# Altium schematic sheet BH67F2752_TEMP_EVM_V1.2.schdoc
size 304 x 228 mm; PageSetup: Record=PageOptions¦CenterHorizontal=True¦CenterVertical=True¦PrintScale=0.87¦XCorrection=1.00¦YCorrection=1.00¦PrintKind=1¦BorderSize=5000000¦LeftOffset=0¦BottomOffset=0¦Orientation=2¦PaperLength=2970¦PaperWidth=2100¦Scale=100¦PaperSource=7¦PrintQuality=600¦MediaType=1¦DitherType=10¦PaperKind=A4¦PrintScaleMode=1
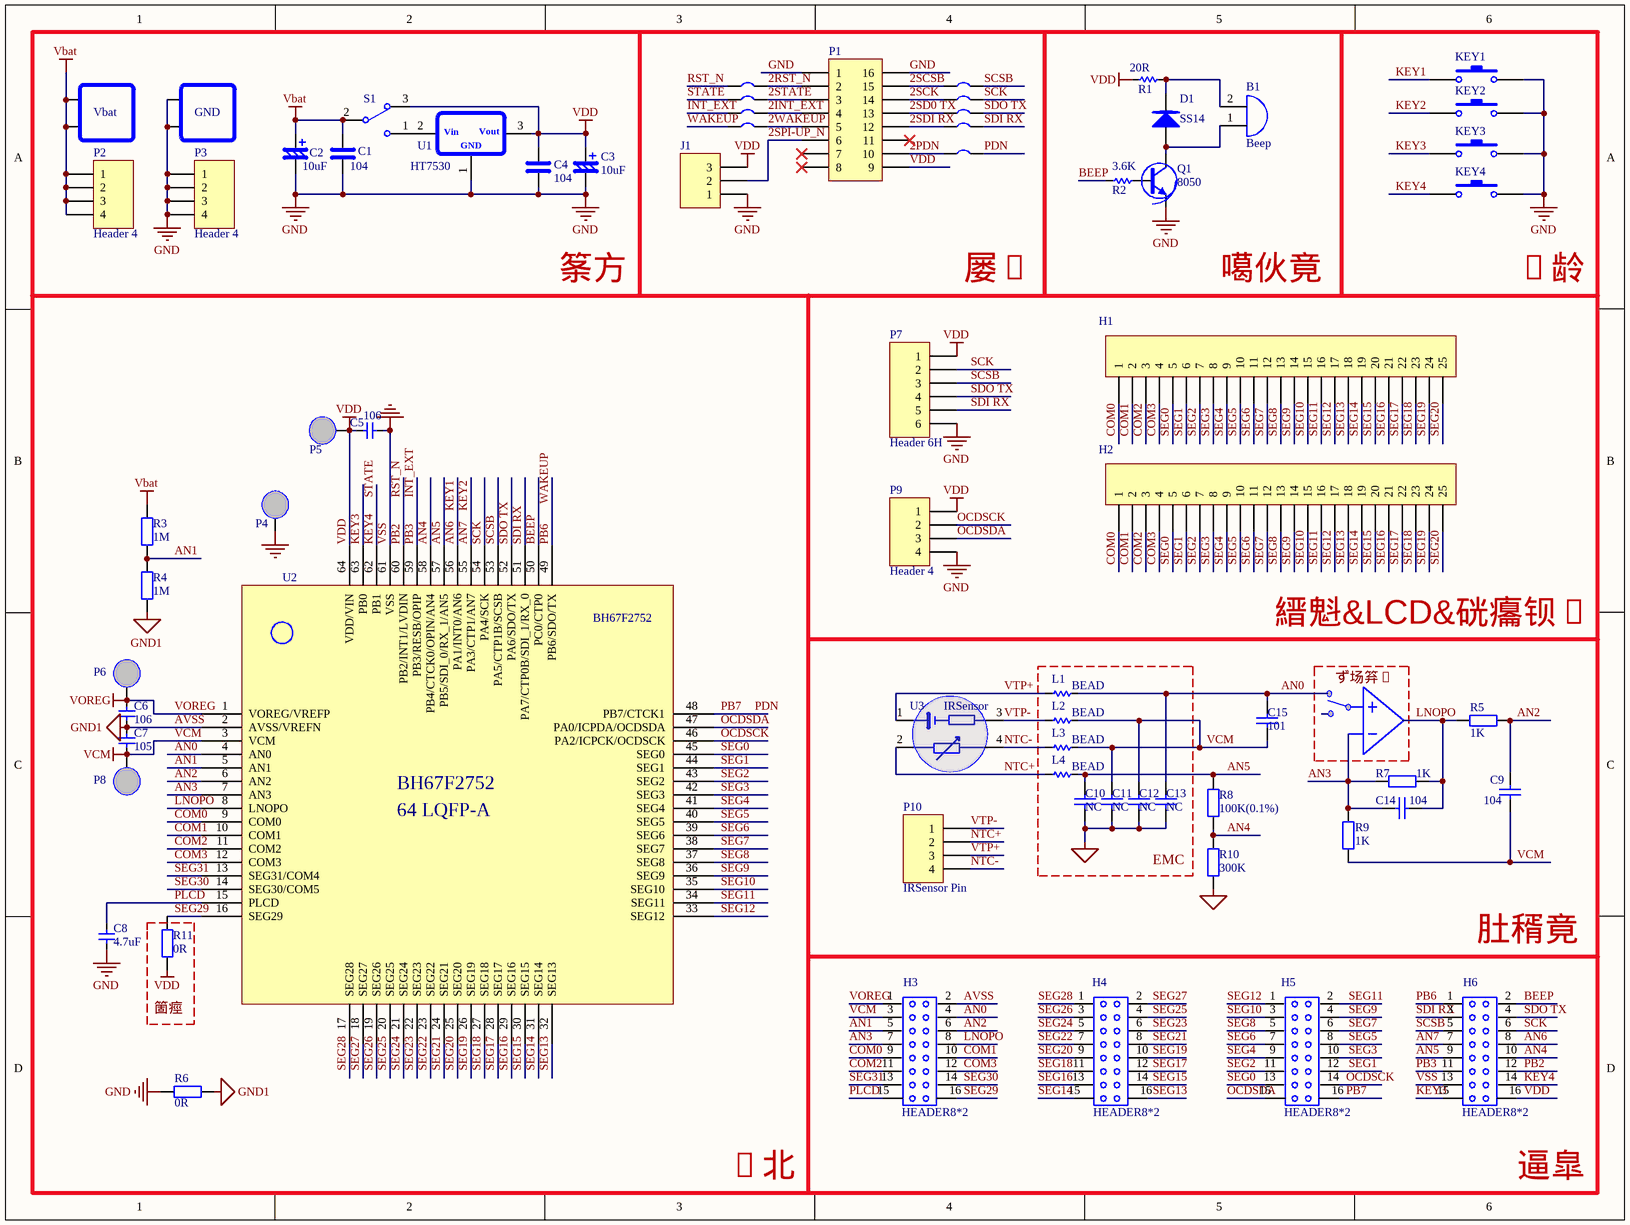
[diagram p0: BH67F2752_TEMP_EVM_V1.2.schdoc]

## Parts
B1  Beep  [BEEP_12mm]
C1  value 104  [C0805]  (hidden comment: CAPACITOR)
C2  Vaule: 10uF  [C0805]  (hidden comment: ECAP)
C3  Vaule: 10uF  [C0805]  (hidden comment: ECAP)
C4  value 104  [C0805]  (hidden comment: CAPACITOR)
C5  106  [CAP_0603]
C6  106  [CAP_0603]
C7  105  [CAP_0603]
C8  4.7uF  [CAP_0603]
C9  104  [CAP_0603]
C10  NC  [CAP_0603]
C11  NC  [CAP_0603]
C12  NC  [CAP_0603]
C13  NC  [CAP_0603]
C14  104  [CAP_0603]
C15  101  [CAP_0603]
D1  SS14  [DIODE]
GND  CONNET*2  [CLIP POWER PIN]  (value not drawn)  (no BOM)
H1  HEADER36  [Header25(2mm) - duplicate]  (value not drawn)
H2  HEADER36  [Header252.54mm)]  (value not drawn)
H3  HEADER8*2  [HEAD2X8]  (no BOM)
H4  HEADER8*2  [2HEAD2X8]  (no BOM)
H5  HEADER8*2  [3HEAD2X8]  (no BOM)
H6  HEADER8*2  [4HEAD2X8 - duplicate]  (no BOM)
INT_EX1  JUMPER  [JUMP_2]  (value not drawn)  (no BOM)
J1  Header 3  [JUMP_3]  (value not drawn)
KEY1  SW-PB  [AN66]  (value not drawn)
KEY2  SW-PB  [AN66]  (value not drawn)
KEY3  SW-PB  [AN66]  (value not drawn)
KEY4  SW-PB  [AN66]  (value not drawn)
L1  BEAD  [RES_0603]
L2  BEAD  [RES_0603]
L3  BEAD  [RES_0603]
L4  BEAD  [RES_0603]
P1  Header 8X2A  [BC7602]  (value not drawn)
P2  Header 4  [HDR1X4]
P3  Header 4  [HDR1X4]
P4  PAD  [PAD]  (value not drawn)
P5  PAD  [PAD]  (value not drawn)
P6  PAD  [PAD]  (value not drawn)
P7  Header 6H  [HEAD1X6]
P8  PAD  [PAD]  (value not drawn)
P9  Header 4  [HDR1X4]
P10  IRSensor Pin  [HDR1X4]
PDN1  JUMPER  [JUMP_2]  (value not drawn)  (no BOM)
Q1  8050  [SOT-23]
R1  20R  [RES_0603]
R2  3.6K  [RES_0603]
R3  value 1M  [RES_0603]  (hidden comment: RES0603)
R4  value 1M  [RES_0603]  (hidden comment: RES0603)
R5  value 1K  [RES_0603]  (hidden comment: RES0603)
R6  value 0R  [RES_0603]  (hidden comment: RES0603)
R7  value 1K  [RES_0603]  (hidden comment: RES0603)
R8  value 100K(0.1%)  [RES_0603]  (hidden comment: RES0603)
R9  value 1K  [RES_0603]  (hidden comment: RES0603)
R10  value 300K  [RES_0603]  (hidden comment: RES0603)
R11  value 0R  [RES_0603]  (hidden comment: RES0603)
RST_N1  JUMPER  [JUMP_2]  (value not drawn)  (no BOM)
S1  SW-3  [JUMP_3]  (value not drawn)
SCK1  JUMPER  [JUMP_2]  (value not drawn)  (no BOM)
SCS1  JUMPER  [JUMP_2]  (value not drawn)  (no BOM)
SDIRX1  JUMPER  [JUMP_2]  (value not drawn)  (no BOM)
SDOTX1  JUMPER  [JUMP_2]  (value not drawn)  (no BOM)
STATE1  JUMPER  [JUMP_2]  (value not drawn)  (no BOM)
U1  HT7530  [SOT89M]
U2  BH67F2752  [64PIN(LQFP)]
U3  IRSensor  [TS318_115]
Vbat  CONNET*2  [CLIP POWER PIN]  (value not drawn)  (no BOM)
WAKE1  JUMPER  [JUMP_2]  (value not drawn)  (no BOM)

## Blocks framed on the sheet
EMC: C10-C13 L1-L4
箇痙: R11

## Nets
AVSS: C6.2 C7.1 C10.2 C11.2 C12.2 C13.2 H3.2 R4.2 R6.1 R10.2 U2.2(AVSS/VREFN)  [also labelled GND1]
GND: C1.1 C2.2 C3.2 C4.1 C5.1 C8.2 GND.1 GND.2 H6.13 J1.1 KEY1.2 KEY2.2 KEY3.2 KEY4.2 P1.1 P1.16 P3.1 P3.2 P3.3 P3.4 P4.1 P7.6 P9.4 Q1.2(E) R6.2 U1.1 U2.61(VSS)  [also labelled VSS]
Vbat: C1.2 C2.1 P2.1 P2.2 P2.3 P2.4 R3.1 S1.2 Vbat.1 Vbat.2
VCM: C7.2 C9.1 C11.1 C12.1 C15.2 H3.3 L2.2 L3.2 P8.1 R9.1 U2.3(VCM)
VDD: C3.1 C4.2 C5.2 H6.16 J1.3 P1.9 P5.1 P7.1 P9.1 R1.2 S1.3 U1.3 U2.64(VDD/VIN)
VOREG: C6.1 H3.1 P6.1 U2.1(VOREG/VREFP)
2INT_EXT: INT_EX1.2 P1.4
2PDN: P1.10 PDN1.2
2RST_N: P1.2 RST_N1.2
2SCK: P1.14 SCK1.2
2SCSB: P1.15 SCS1.2
2SD0 TX: P1.13 SDOTX1.2
2SDI RX: P1.12 SDIRX1.2
2SPI-UP_N: J1.2 P1.6
2STATE: P1.3 STATE1.2
2WAKEUP: P1.5 WAKE1.2
AN0: C13.1 C15.1 H3.4 L1.2 U2.4(AN0)
AN1: H3.5 R3.2 R4.1 U2.5(AN1)
AN2: C9.2 H3.6 R5.2 U2.6(AN2)
AN3: C14.2 H3.7 R7.1 R9.2 U2.7(AN3)
AN4: H6.10 R8.2 R10.1 U2.58(PB4/CTCK0/OPIN/AN4)
AN5: C10.1 H6.9 L4.2 R8.1 U2.57(PB5/SDI_0/RX_1/AN5)
AN6: H6.8 KEY1.1 U2.56(PA1/INT0/AN6)  [also labelled KEY1]
AN7: H6.7 KEY2.1 U2.55(PA3/CTP1/AN7)  [also labelled KEY2]
BEEP: H6.2 R2.1 U2.50(PC0/CTP0)
COM0: H1.1 H2.1 H3.9 U2.9(COM0)
COM1: H1.2 H2.2 H3.10 U2.10(COM1)
COM2: H1.3 H2.3 H3.11 U2.11(COM2)
COM3: H1.4 H2.4 H3.12 U2.12(COM3)
INT_EXT: H6.11 INT_EX1.1 U2.59(PB3/RESB/OPIP)  [also labelled PB3]
KEY3: H6.15 KEY3.1 U2.63(PB0)
KEY4: H6.14 KEY4.1 STATE1.1 U2.62(PB1)  [also labelled STATE]
LNOPO: C14.1 H3.8 R5.1 R7.2 U2.8(LNOPO)
NTC+: L4.1 P10.2 U3.2
NTC-: L3.1 P10.4 U3.4
OCDSCK: H5.14 P9.2 U2.46(PA2/ICPCK/OCDSCK)
OCDSDA: H5.15 P9.3 U2.47(PA0/ICPDA/OCDSDA)
PB2: H6.12 RST_N1.1 U2.60(PB2/INT1/LVDIN)  [also labelled RST_N]
PB6: H6.1 U2.49(PB6/SDO/TX) WAKE1.1  [also labelled WAKEUP]
PB7: H5.16 PDN1.1 U2.48(PB7/CTCK1)  [also labelled PDN]
PLCD: C8.1 H3.15 U2.15(PLCD)
SCK: H6.6 P7.2 SCK1.1 U2.54(PA4/SCK)
SCSB: H6.5 P7.3 SCS1.1 U2.53(PA5/CTP1B/SCSB)
SDI RX: H6.3 P7.5 SDIRX1.1 U2.51(PA7/CTP0B/SDI_1/RX_0)
SDO TX: H6.4 P7.4 SDOTX1.1 U2.52(PA6/SDO/TX)
SEG0: H1.5 H2.5 H5.13 U2.45(SEG0)
SEG1: H1.6 H2.6 H5.12 U2.44(SEG1)
SEG2: H1.7 H2.7 H5.11 U2.43(SEG2)
SEG3: H1.8 H2.8 H5.10 U2.42(SEG3)
SEG4: H1.9 H2.9 H5.9 U2.41(SEG4)
SEG5: H1.10 H2.10 H5.8 U2.40(SEG5)
SEG6: H1.11 H2.11 H5.7 U2.39(SEG6)
SEG7: H1.12 H2.12 H5.6 U2.38(SEG7)
SEG8: H1.13 H2.13 H5.5 U2.37(SEG8)
SEG9: H1.14 H2.14 H5.4 U2.36(SEG9)
SEG10: H1.15 H2.15 H5.3 U2.35(SEG10)
SEG11: H1.16 H2.16 H5.2 U2.34(SEG11)
SEG12: H1.17 H2.17 H5.1 U2.33(SEG12)
SEG13: H1.18 H2.18 H4.16 U2.32(SEG13)
SEG14: H1.19 H2.19 H4.15 U2.31(SEG14)
SEG15: H1.20 H2.20 H4.14 U2.30(SEG15)
SEG16: H1.21 H2.21 H4.13 U2.29(SEG16)
SEG17: H1.22 H2.22 H4.12 U2.28(SEG17)
SEG18: H1.23 H2.23 H4.11 U2.27(SEG18)
SEG19: H1.24 H2.24 H4.10 U2.26(SEG19)
SEG20: H1.25 H2.25 H4.9 U2.25(SEG20)
SEG21: H4.8 U2.24(SEG21)
SEG22: H4.7 U2.23(SEG22)
SEG23: H4.6 U2.22(SEG23)
SEG24: H4.5 U2.21(SEG24)
SEG25: H4.4 U2.20(SEG25)
SEG26: H4.3 U2.19(SEG26)
SEG27: H4.2 U2.18(SEG27)
SEG28: H4.1 U2.17(SEG28)
SEG29: H3.16 R11.2 U2.16(SEG29)
SEG30: H3.14 U2.14(SEG30/COM5)
SEG31: H3.13 U2.13(SEG31/COM4)
VTP+: L1.1 P10.3 U3.1
VTP-: L2.1 P10.1 U3.3
NetB1_1: B1.1 D1.1(A) Q1.3(C)
NetB1_2: B1.2 D1.2(K) R1.1
NetQ1_1: Q1.1(B) R2.2
NetS1_1: S1.1 U1.2

Not connected (* = marked no-connect by the designer): P1 7* 8* 11*; R11 1

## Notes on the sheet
- 筿方
- 屡
- 噶伙竟
- 龄
- 縉魁&LCD&硄癟钡
- ず场笲
- 肚稰竟
- 北
- (near H6) 逼皐
- Labels drawn without touching a wire or pin: VDD

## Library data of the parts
C2 C3 = ECAP: Capacitor
C5-C8 = CAP(1)
C9 C14 = Cap: Capacitor
C10-C13 C15 = Cap: Capacitor; Value: 104
D1 = DIODE(1)
GND Vbat = CONNET*2: 2CONNET*2.54
INT_EX1 PDN1 RST_N1 SCK1 SCS1 SDIRX1 SDOTX1 STATE1 WAKE1 = JUMPER2: JUMPER FOR BREAK CIRCUTS
J1 = Header 3: Header, 3-Pin
KEY1-KEY4 = SW-PB: Switch
L1-L4 R1 R2 = RES(1)
P1 = Header 8X2A: Header, 8-Pin, Dual row
P2 P3 P9 P10 = Header 4: Header, 4-Pin
P7 = Header 6H: Header, 6-Pin, Right Angle
Q1 = NPN(1)
R3-R11 = Res2: Resistor
U1 = LDO: Low Drop Regulator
